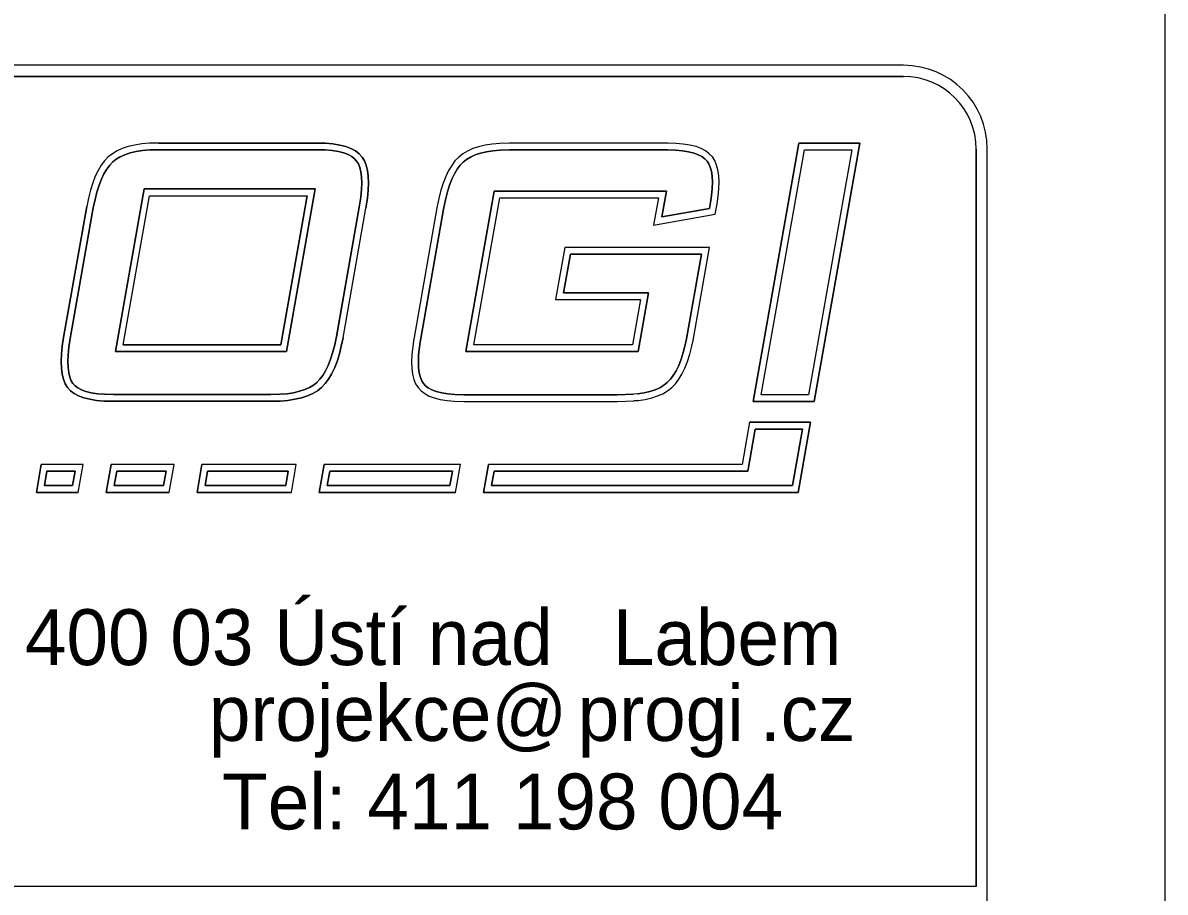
# Model space of a CAD drawing. Extents: x 377 to 692, y 94 to 238.
# Drawn here: x 672.83 to 692.24, y 115.67 to 130.46 of the extents above; entities that cross this region are included whole.
import ezdxf

# ---------------------------------------------------------------- set-up
doc = ezdxf.new("R2010")
doc.units = 0
doc.layers.add('000_rozpiska', color=7, linetype='Continuous')

msp = doc.modelspace()

# ---------------------------------------------------------------- linework, layer by layer
at = {"layer": '000_rozpiska'}
for p, q in [((692.243, 93.878), (692.243, 238.378)), ((687.796, 129.736), (601.346, 129.736)), ((687.796, 129.736), (601.346, 129.736)), ((687.796, 129.546), (660.721, 129.546)), ((680.575, 128.352), (680.475, 128.319)), ((680.687, 128.378), (680.575, 128.352)), ((680.805, 128.396), (680.687, 128.378)), ((680.938, 128.408), (680.805, 128.396)), ((681.097, 128.411), (680.938, 128.408)), ((683.794, 128.411), (681.097, 128.411)), ((683.928, 128.408), (683.794, 128.411)), ((684.052, 128.397), (683.928, 128.408)), ((684.165, 128.379), (684.052, 128.397)), ((684.27, 128.353), (684.165, 128.379)), ((684.356, 128.32), (684.27, 128.353)), ((685.242, 124.021), (686.015, 128.411)), ((686.015, 128.411), (687.052, 128.411)), ((687.052, 128.411), (686.279, 124.021)), ((674.357, 128.093), (674.416, 128.139)), ((674.416, 128.139), (674.482, 128.179)), ((674.482, 128.179), (674.56, 128.215)), ((674.56, 128.215), (674.651, 128.245)), ((674.651, 128.245), (674.752, 128.268)), ((674.752, 128.268), (674.864, 128.286)), ((674.864, 128.286), (674.988, 128.296)), ((674.988, 128.296), (675.142, 128.3)), ((675.142, 128.3), (677.833, 128.3)), ((677.833, 128.3), (677.966, 128.296)), ((677.966, 128.296), (678.086, 128.286)), ((678.086, 128.286), (678.192, 128.269)), ((678.192, 128.269), (678.282, 128.245)), ((678.282, 128.245), (678.356, 128.218)), ((678.356, 128.218), (678.42, 128.184)), ((678.42, 128.184), (678.465, 128.148)), ((678.465, 128.148), (678.502, 128.107)), ((680.236, 128.175), (680.173, 128.109)), ((680.306, 128.23), (680.236, 128.175)), ((680.384, 128.278), (680.306, 128.23)), ((680.438, 128.176), (680.371, 128.136)), ((680.475, 128.319), (680.384, 128.278)), ((680.517, 128.213), (680.438, 128.176)), ((680.606, 128.242), (680.517, 128.213)), ((680.709, 128.266), (680.606, 128.242)), ((680.819, 128.283), (680.709, 128.266)), ((680.944, 128.294), (680.819, 128.283)), ((681.098, 128.297), (680.944, 128.294)), ((683.792, 128.297), (681.098, 128.297)), ((683.921, 128.294), (683.792, 128.297)), ((684.038, 128.284), (683.921, 128.294)), ((684.142, 128.267), (684.038, 128.284)), ((684.236, 128.244), (684.142, 128.267)), ((684.309, 128.216), (684.236, 128.244)), ((684.371, 128.184), (684.309, 128.216)), ((684.432, 128.28), (684.356, 128.32)), ((684.42, 128.148), (684.371, 128.184)), ((684.458, 128.107), (684.42, 128.148)), ((684.496, 128.233), (684.432, 128.28)), ((684.549, 128.177), (684.496, 128.233)), ((684.588, 128.115), (684.549, 128.177)), ((685.378, 124.135), (686.111, 128.297)), ((686.111, 128.297), (686.916, 128.297)), ((686.916, 128.297), (686.183, 124.135)), ((689.031, 115.77), (689.031, 128.311)), ((689.221, 98.325), (689.221, 128.311)), ((689.221, 98.325), (689.221, 128.311)), ((674.207, 127.893), (674.255, 127.972)), ((674.255, 127.972), (674.305, 128.038)), ((674.305, 128.038), (674.357, 128.093)), ((678.502, 128.107), (678.532, 128.059)), ((678.532, 128.059), (678.555, 128)), ((678.555, 128), (678.574, 127.924)), ((680.064, 127.946), (680.015, 127.845)), ((680.117, 128.034), (680.064, 127.946)), ((680.173, 128.109), (680.117, 128.034)), ((680.212, 127.97), (680.165, 127.892)), ((680.261, 128.035), (680.212, 127.97)), ((680.313, 128.09), (680.261, 128.035)), ((680.371, 128.136), (680.313, 128.09)), ((684.487, 128.062), (684.458, 128.107)), ((684.512, 128.003), (684.487, 128.062)), ((684.531, 127.934), (684.512, 128.003)), ((684.62, 128.04), (684.588, 128.115)), ((684.643, 127.958), (684.62, 128.04)), ((684.657, 127.862), (684.643, 127.958)), ((674.123, 127.698), (674.164, 127.802)), ((674.164, 127.802), (674.207, 127.893)), ((678.574, 127.924), (678.585, 127.838)), ((678.585, 127.838), (678.589, 127.735)), ((680.015, 127.845), (679.972, 127.732)), ((680.12, 127.799), (680.08, 127.695)), ((680.165, 127.892), (680.12, 127.799)), ((684.543, 127.85), (684.531, 127.934)), ((684.549, 127.751), (684.543, 127.85)), ((684.546, 127.643), (684.549, 127.751)), ((684.663, 127.752), (684.657, 127.862)), ((684.659, 127.636), (684.663, 127.752)), ((674.055, 127.453), (674.087, 127.581)), ((674.087, 127.581), (674.123, 127.698)), ((674.401, 124.868), (674.888, 127.633)), ((674.888, 127.633), (677.796, 127.633)), ((677.309, 124.868), (677.796, 127.633)), ((678.584, 127.623), (678.572, 127.492)), ((678.589, 127.735), (678.584, 127.623)), ((679.935, 127.613), (679.899, 127.472)), ((679.972, 127.732), (679.935, 127.613)), ((680.044, 127.582), (680.01, 127.447)), ((680.08, 127.695), (680.044, 127.582)), ((680.357, 124.868), (680.838, 127.596)), ((680.838, 127.596), (683.766, 127.596)), ((683.766, 127.596), (683.689, 127.159)), ((684.534, 127.524), (684.546, 127.643)), ((684.647, 127.51), (684.659, 127.636)), ((674.026, 127.313), (674.055, 127.453)), ((674.536, 124.982), (674.983, 127.519)), ((674.983, 127.519), (677.66, 127.519)), ((677.213, 124.982), (677.66, 127.519)), ((678.572, 127.492), (678.546, 127.323)), ((679.882, 127.39), (679.866, 127.312)), ((679.899, 127.472), (679.882, 127.39)), ((679.994, 127.367), (679.978, 127.29)), ((680.01, 127.447), (679.994, 127.367)), ((680.493, 124.982), (680.933, 127.482)), ((680.933, 127.482), (683.63, 127.482)), ((683.63, 127.482), (683.548, 127.018)), ((684.499, 127.303), (684.516, 127.401)), ((684.516, 127.401), (684.534, 127.524)), ((684.597, 127.205), (684.628, 127.383)), ((684.628, 127.383), (684.647, 127.51)), ((673.522, 125.109), (673.914, 127.336)), ((673.635, 125.091), (674.026, 127.313)), ((678.546, 127.323), (678.158, 125.12)), ((678.271, 125.101), (678.659, 127.306)), ((679.866, 127.312), (679.478, 125.11)), ((679.978, 127.29), (679.591, 125.093)), ((683.548, 127.018), (684.597, 127.205)), ((683.689, 127.159), (684.499, 127.303)), ((682.038, 126.637), (681.883, 125.755)), ((684.497, 126.637), (682.038, 126.637)), ((684.219, 125.059), (684.497, 126.637)), ((682.134, 126.523), (682.019, 125.869)), ((684.361, 126.523), (682.134, 126.523)), ((684.107, 125.082), (684.361, 126.523)), ((682.019, 125.869), (683.461, 125.869)), ((683.461, 125.869), (683.285, 124.868)), ((681.883, 125.755), (683.326, 125.755)), ((683.326, 125.755), (683.189, 124.982)), ((673.612, 124.944), (673.635, 125.091)), ((678.159, 125.125), (678.129, 124.983)), ((679.47, 125.05), (679.456, 124.955)), ((679.478, 125.11), (679.47, 125.05)), ((679.583, 125.034), (679.569, 124.941)), ((679.591, 125.093), (679.583, 125.034)), ((684.085, 124.985), (684.107, 125.082)), ((684.196, 124.958), (684.219, 125.059)), ((673.599, 124.813), (673.612, 124.944)), ((674.401, 124.868), (677.309, 124.868)), ((674.536, 124.982), (677.213, 124.982)), ((678.099, 124.861), (678.06, 124.738)), ((678.129, 124.983), (678.099, 124.861)), ((679.456, 124.955), (679.442, 124.82)), ((679.569, 124.941), (679.556, 124.812)), ((683.285, 124.868), (680.357, 124.868)), ((683.189, 124.982), (680.493, 124.982)), ((684.015, 124.736), (684.052, 124.853)), ((684.052, 124.853), (684.085, 124.985)), ((684.162, 124.822), (684.196, 124.958)), ((673.594, 124.698), (673.599, 124.813)), ((673.598, 124.595), (673.594, 124.698)), ((678.06, 124.738), (678.019, 124.633)), ((679.442, 124.82), (679.437, 124.698)), ((679.437, 124.698), (679.441, 124.584)), ((679.556, 124.812), (679.552, 124.698)), ((679.552, 124.698), (679.555, 124.593)), ((683.975, 124.63), (684.015, 124.736)), ((684.079, 124.585), (684.123, 124.699)), ((684.123, 124.699), (684.162, 124.822)), ((673.609, 124.507), (673.598, 124.595)), ((673.628, 124.433), (673.609, 124.507)), ((677.928, 124.463), (677.879, 124.397)), ((677.975, 124.541), (677.928, 124.463)), ((678.019, 124.633), (677.975, 124.541)), ((679.441, 124.584), (679.454, 124.483)), ((679.454, 124.483), (679.476, 124.394)), ((679.555, 124.593), (679.566, 124.504)), ((679.566, 124.504), (679.585, 124.429)), ((683.835, 124.396), (683.884, 124.461)), ((683.884, 124.461), (683.93, 124.538)), ((683.93, 124.538), (683.975, 124.63)), ((683.978, 124.398), (684.031, 124.484)), ((684.031, 124.484), (684.079, 124.585)), ((673.652, 124.373), (673.628, 124.433)), ((673.68, 124.326), (673.652, 124.373)), ((673.716, 124.287), (673.68, 124.326)), ((673.764, 124.251), (673.716, 124.287)), ((677.702, 124.258), (677.622, 124.222)), ((677.769, 124.297), (677.702, 124.258)), ((677.826, 124.342), (677.769, 124.297)), ((677.879, 124.397), (677.826, 124.342)), ((679.476, 124.394), (679.505, 124.321)), ((679.505, 124.321), (679.545, 124.255)), ((679.545, 124.255), (679.596, 124.199)), ((679.585, 124.429), (679.607, 124.372)), ((679.607, 124.372), (679.637, 124.324)), ((679.637, 124.324), (679.673, 124.284)), ((679.673, 124.284), (679.72, 124.25)), ((683.653, 124.253), (683.724, 124.294)), ((683.724, 124.294), (683.781, 124.34)), ((683.781, 124.34), (683.835, 124.396)), ((683.788, 124.2), (683.858, 124.255)), ((683.858, 124.255), (683.922, 124.322)), ((683.922, 124.322), (683.978, 124.398)), ((673.824, 124.219), (673.764, 124.251)), ((673.9, 124.191), (673.824, 124.219)), ((673.99, 124.168), (673.9, 124.191)), ((674.096, 124.151), (673.99, 124.168)), ((674.214, 124.141), (674.096, 124.151)), ((674.37, 124.137), (674.214, 124.141)), ((677.043, 124.137), (674.37, 124.137)), ((677.196, 124.141), (677.043, 124.137)), ((677.319, 124.151), (677.196, 124.141)), ((677.431, 124.169), (677.319, 124.151)), ((677.533, 124.192), (677.431, 124.169)), ((677.622, 124.222), (677.533, 124.192)), ((679.596, 124.199), (679.659, 124.153)), ((679.659, 124.153), (679.735, 124.112)), ((679.72, 124.25), (679.782, 124.216)), ((679.735, 124.112), (679.822, 124.079)), ((679.782, 124.216), (679.856, 124.188)), ((679.822, 124.079), (679.924, 124.054)), ((679.856, 124.188), (679.947, 124.166)), ((679.947, 124.166), (680.053, 124.149)), ((680.053, 124.149), (680.172, 124.139)), ((680.172, 124.139), (680.325, 124.135)), ((680.325, 124.135), (682.932, 124.135)), ((682.932, 124.135), (683.207, 124.144)), ((683.274, 124.149), (683.207, 124.144)), ((683.274, 124.149), (683.387, 124.166)), ((683.387, 124.166), (683.486, 124.189)), ((683.408, 124.054), (683.517, 124.079)), ((683.486, 124.189), (683.576, 124.219)), ((683.517, 124.079), (683.617, 124.113)), ((683.576, 124.219), (683.653, 124.253)), ((683.617, 124.113), (683.705, 124.151)), ((683.705, 124.151), (683.788, 124.2)), ((686.183, 124.135), (685.378, 124.135)), ((679.924, 124.054), (680.039, 124.036)), ((680.039, 124.036), (680.166, 124.025)), ((680.166, 124.025), (680.324, 124.021)), ((680.324, 124.021), (682.934, 124.021)), ((682.934, 124.021), (683.213, 124.03)), ((683.287, 124.036), (683.213, 124.03)), ((683.287, 124.036), (683.408, 124.054)), ((686.279, 124.021), (685.242, 124.021)), ((685.179, 123.665), (685.053, 122.949)), ((685.275, 123.551), (685.149, 122.835)), ((685.179, 123.665), (686.216, 123.665)), ((685.275, 123.551), (686.08, 123.551)), ((686.08, 123.551), (685.911, 122.588)), ((686.216, 123.665), (686.006, 122.474)), ((673.058, 122.474), (673.142, 122.949)), ((673.854, 122.949), (673.142, 122.949)), ((673.77, 122.474), (673.854, 122.949)), ((674.245, 122.474), (674.329, 122.949)), ((675.398, 122.949), (674.329, 122.949)), ((675.314, 122.474), (675.398, 122.949)), ((675.789, 122.474), (675.873, 122.949)), ((677.476, 122.949), (675.873, 122.949)), ((677.392, 122.474), (677.476, 122.949)), ((677.867, 122.474), (677.951, 122.949)), ((680.267, 122.949), (677.951, 122.949)), ((680.183, 122.474), (680.267, 122.949)), ((680.658, 122.474), (680.742, 122.949)), ((685.053, 122.949), (680.742, 122.949)), ((673.194, 122.588), (673.237, 122.835)), ((673.718, 122.835), (673.237, 122.835)), ((673.675, 122.588), (673.718, 122.835)), ((674.381, 122.588), (674.425, 122.835)), ((675.262, 122.835), (674.425, 122.835)), ((675.218, 122.588), (675.262, 122.835)), ((675.925, 122.588), (675.968, 122.835)), ((677.34, 122.835), (675.968, 122.835)), ((677.297, 122.588), (677.34, 122.835)), ((678.003, 122.588), (678.047, 122.835)), ((680.131, 122.835), (678.047, 122.835)), ((680.087, 122.588), (680.131, 122.835)), ((680.794, 122.588), (680.837, 122.835)), ((685.149, 122.835), (680.837, 122.835)), ((673.675, 122.588), (673.194, 122.588)), ((675.218, 122.588), (674.381, 122.588)), ((677.297, 122.588), (675.925, 122.588)), ((680.087, 122.588), (678.003, 122.588)), ((685.911, 122.588), (680.794, 122.588)), ((673.77, 122.474), (673.058, 122.474)), ((675.314, 122.474), (674.245, 122.474)), ((677.392, 122.474), (675.789, 122.474)), ((680.183, 122.474), (677.867, 122.474)), ((686.006, 122.474), (680.658, 122.474)), ((689.031, 115.77), (660.721, 115.77))]:
    msp.add_line(p, q, dxfattribs=at)
for points in [[(660.721, 115.77), (660.721, 129.546), (687.796, 129.546)], [(678.216, 128.38), (678.1, 128.399), (677.972, 128.41), (677.836, 128.414), (675.141, 128.414), (674.982, 128.41), (674.851, 128.399), (674.73, 128.38), (674.62, 128.355), (674.519, 128.321), (674.429, 128.28), (674.351, 128.233), (674.279, 128.177), (674.217, 128.111), (674.16, 128.036), (674.107, 127.947), (674.06, 127.848), (674.016, 127.736), (673.977, 127.612), (673.944, 127.478), (673.914, 127.336), (673.522, 125.109), (673.499, 124.959), (673.485, 124.821), (673.48, 124.698), (673.484, 124.586), (673.497, 124.486), (673.519, 124.398), (673.549, 124.321), (673.589, 124.257), (673.639, 124.202), (673.702, 124.155), (673.777, 124.115), (673.866, 124.082), (673.967, 124.056), (674.082, 124.038), (674.208, 124.027), (674.367, 124.023), (677.044, 124.023), (677.202, 124.027), (677.332, 124.038), (677.453, 124.057), (677.564, 124.083), (677.664, 124.115), (677.755, 124.156), (677.834, 124.203), (677.903, 124.257), (677.966, 124.323), (678.023, 124.399), (678.075, 124.486), (678.124, 124.587), (678.168, 124.7), (678.209, 124.83), (678.24, 124.958), (678.271, 125.101), (678.659, 127.306), (678.685, 127.478), (678.698, 127.615), (678.703, 127.735), (678.699, 127.848), (678.686, 127.945), (678.664, 128.035), (678.634, 128.11), (678.594, 128.175), (678.543, 128.232), (678.482, 128.28), (678.403, 128.322), (678.317, 128.354), (678.216, 128.38)], [(675.141, 128.414), (674.982, 128.41), (674.851, 128.399), (674.73, 128.38), (674.62, 128.355), (674.519, 128.321), (674.429, 128.28), (674.351, 128.233), (674.279, 128.177), (674.217, 128.111), (674.16, 128.036), (674.107, 127.947), (674.06, 127.848), (674.016, 127.736), (673.977, 127.612), (673.944, 127.478), (673.914, 127.336)], [(675.141, 128.414), (677.836, 128.414), (677.972, 128.41), (678.1, 128.399), (678.216, 128.38), (678.317, 128.354), (678.403, 128.322), (678.482, 128.28), (678.543, 128.232), (678.594, 128.175), (678.634, 128.11), (678.664, 128.035), (678.686, 127.945), (678.699, 127.848), (678.703, 127.735), (678.698, 127.615), (678.685, 127.478), (678.659, 127.306)], [(684.27, 128.353), (684.165, 128.379), (684.052, 128.397), (683.928, 128.408), (683.794, 128.411), (681.097, 128.411), (680.938, 128.408), (680.805, 128.396), (680.687, 128.378), (680.575, 128.352), (680.475, 128.319), (680.384, 128.278), (680.306, 128.23), (680.236, 128.175), (680.173, 128.109), (680.117, 128.034), (680.064, 127.946), (680.015, 127.845), (679.972, 127.732), (679.935, 127.613), (679.899, 127.472), (679.882, 127.39), (679.866, 127.312), (679.478, 125.11), (679.47, 125.05), (679.456, 124.955), (679.442, 124.82), (679.437, 124.698), (679.441, 124.584), (679.454, 124.483), (679.476, 124.394), (679.505, 124.321), (679.545, 124.255), (679.596, 124.199), (679.659, 124.153), (679.735, 124.112), (679.822, 124.079), (679.924, 124.054), (680.039, 124.036), (680.166, 124.025), (680.324, 124.021), (682.934, 124.021), (683.213, 124.03), (683.287, 124.036), (683.408, 124.054), (683.517, 124.079), (683.617, 124.113), (683.705, 124.151), (683.788, 124.2), (683.858, 124.255), (683.922, 124.322), (683.978, 124.398), (684.031, 124.484), (684.079, 124.585), (684.123, 124.699), (684.162, 124.822), (684.196, 124.958), (684.219, 125.059), (684.497, 126.637), (682.038, 126.637), (681.883, 125.755), (683.326, 125.755), (683.189, 124.982), (680.493, 124.982), (680.933, 127.482), (683.63, 127.482), (683.548, 127.018), (684.597, 127.205), (684.628, 127.383), (684.647, 127.51), (684.659, 127.636), (684.663, 127.752), (684.657, 127.862), (684.643, 127.958), (684.62, 128.04), (684.588, 128.115), (684.549, 128.177), (684.496, 128.233), (684.432, 128.28), (684.356, 128.32), (684.27, 128.353)], [(687.052, 128.411), (686.015, 128.411), (685.242, 124.021), (686.279, 124.021), (687.052, 128.411)], [(689.031, 128.311), (689.031, 115.77), (660.721, 115.77)], [(678.589, 127.735), (678.585, 127.838), (678.574, 127.924), (678.555, 128), (678.532, 128.059), (678.502, 128.107), (678.465, 128.148), (678.42, 128.184), (678.356, 128.218), (678.282, 128.245), (678.192, 128.269), (678.086, 128.286), (677.966, 128.296), (677.833, 128.3), (675.142, 128.3), (674.988, 128.296), (674.864, 128.286), (674.752, 128.268), (674.651, 128.245), (674.56, 128.215), (674.482, 128.179), (674.416, 128.139), (674.357, 128.093), (674.305, 128.038), (674.255, 127.972), (674.207, 127.893), (674.164, 127.802), (674.123, 127.698), (674.087, 127.581), (674.055, 127.453), (674.026, 127.313), (673.635, 125.091), (673.612, 124.944), (673.599, 124.813), (673.594, 124.698), (673.598, 124.595), (673.609, 124.507), (673.628, 124.433), (673.652, 124.373), (673.68, 124.326), (673.716, 124.287), (673.764, 124.251), (673.824, 124.219), (673.9, 124.191), (673.99, 124.168), (674.096, 124.151), (674.214, 124.141), (674.37, 124.137), (677.043, 124.137), (677.196, 124.141), (677.319, 124.151), (677.431, 124.169), (677.533, 124.192), (677.622, 124.222), (677.702, 124.258), (677.769, 124.297), (677.826, 124.342), (677.879, 124.397), (677.928, 124.463), (677.975, 124.541), (678.019, 124.633), (678.06, 124.738), (678.099, 124.861), (678.129, 124.983), (678.159, 125.122), (678.546, 127.323), (678.572, 127.492), (678.584, 127.623), (678.589, 127.735)], [(677.833, 128.3), (677.966, 128.296), (678.086, 128.286), (678.192, 128.269), (678.282, 128.245), (678.356, 128.218), (678.42, 128.184), (678.465, 128.148), (678.502, 128.107), (678.532, 128.059), (678.555, 128), (678.574, 127.924), (678.585, 127.838), (678.589, 127.735), (678.584, 127.623), (678.572, 127.492), (678.546, 127.323), (678.159, 125.122), (678.129, 124.983), (678.099, 124.861), (678.06, 124.738), (678.019, 124.633), (677.975, 124.541), (677.928, 124.463), (677.879, 124.397), (677.826, 124.342), (677.769, 124.297), (677.702, 124.258), (677.622, 124.222), (677.533, 124.192), (677.431, 124.169), (677.319, 124.151), (677.196, 124.141), (677.043, 124.137), (674.37, 124.137), (674.214, 124.141), (674.096, 124.151), (673.99, 124.168), (673.9, 124.191), (673.824, 124.219), (673.764, 124.251), (673.716, 124.287), (673.68, 124.326), (673.652, 124.373), (673.628, 124.433), (673.609, 124.507), (673.598, 124.595), (673.594, 124.698), (673.599, 124.813), (673.612, 124.944), (673.635, 125.091), (674.026, 127.313), (674.055, 127.453), (674.087, 127.581), (674.123, 127.698), (674.164, 127.802), (674.207, 127.893), (674.255, 127.972), (674.305, 128.038), (674.357, 128.093), (674.416, 128.139), (674.482, 128.179), (674.56, 128.215), (674.651, 128.245), (674.752, 128.268), (674.864, 128.286), (674.988, 128.296), (675.142, 128.3), (677.833, 128.3)], [(683.792, 128.297), (683.921, 128.294), (684.038, 128.284), (684.142, 128.267), (684.236, 128.244), (684.309, 128.216), (684.371, 128.184), (684.42, 128.148), (684.458, 128.107), (684.487, 128.062), (684.512, 128.003), (684.531, 127.934), (684.543, 127.85), (684.549, 127.751), (684.546, 127.643), (684.534, 127.524), (684.516, 127.401), (684.499, 127.303), (683.689, 127.159), (683.766, 127.596), (680.838, 127.596), (680.357, 124.868), (683.285, 124.868), (683.461, 125.869), (682.019, 125.869), (682.134, 126.523), (684.361, 126.523), (684.107, 125.082), (684.085, 124.985), (684.052, 124.853), (684.015, 124.736), (683.975, 124.63), (683.93, 124.538), (683.884, 124.461), (683.835, 124.396), (683.781, 124.34), (683.724, 124.294), (683.653, 124.253), (683.576, 124.219), (683.486, 124.189), (683.387, 124.166), (683.274, 124.149), (683.207, 124.144), (682.932, 124.135), (680.325, 124.135), (680.172, 124.139), (680.053, 124.149), (679.947, 124.166), (679.856, 124.188), (679.782, 124.216), (679.72, 124.25), (679.673, 124.284), (679.637, 124.324), (679.607, 124.372), (679.585, 124.429), (679.566, 124.504), (679.555, 124.593), (679.552, 124.698), (679.556, 124.812), (679.569, 124.941), (679.583, 125.034), (679.591, 125.093), (679.978, 127.29), (679.994, 127.367), (680.01, 127.447), (680.044, 127.582), (680.08, 127.695), (680.12, 127.799), (680.165, 127.892), (680.212, 127.97), (680.261, 128.035), (680.313, 128.09), (680.371, 128.136), (680.438, 128.176), (680.517, 128.213), (680.606, 128.242), (680.709, 128.266), (680.819, 128.283), (680.944, 128.294), (681.098, 128.297), (683.792, 128.297)], [(686.916, 128.297), (686.183, 124.135), (685.378, 124.135), (686.111, 128.297), (686.916, 128.297)], [(677.796, 127.633), (677.309, 124.868), (674.401, 124.868), (674.888, 127.633), (677.796, 127.633)], [(677.796, 127.633), (674.888, 127.633), (674.401, 124.868), (677.309, 124.868), (677.796, 127.633)], [(677.66, 127.519), (677.213, 124.982), (674.536, 124.982), (674.983, 127.519), (677.66, 127.519)], [(674.367, 124.023), (674.208, 124.027), (674.082, 124.038), (673.967, 124.056), (673.866, 124.082), (673.777, 124.115), (673.702, 124.155), (673.639, 124.202), (673.589, 124.257), (673.549, 124.321), (673.519, 124.398), (673.497, 124.486), (673.484, 124.586), (673.48, 124.698), (673.485, 124.821), (673.499, 124.959), (673.522, 125.109)], [(678.271, 125.101), (678.24, 124.958), (678.209, 124.83), (678.168, 124.7), (678.124, 124.587), (678.075, 124.486), (678.023, 124.399), (677.966, 124.323), (677.903, 124.257), (677.834, 124.203), (677.755, 124.156), (677.664, 124.115), (677.564, 124.083), (677.453, 124.057), (677.332, 124.038), (677.202, 124.027), (677.044, 124.023), (674.367, 124.023)], [(686.216, 123.665), (685.179, 123.665), (685.053, 122.949), (680.742, 122.949), (680.658, 122.474), (686.006, 122.474), (686.216, 123.665)], [(686.08, 123.551), (685.911, 122.588), (680.794, 122.588), (680.837, 122.835), (685.149, 122.835), (685.275, 123.551), (686.08, 123.551)], [(686.08, 123.551), (685.275, 123.551), (685.149, 122.835), (680.837, 122.835), (680.794, 122.588), (685.911, 122.588), (686.08, 123.551)], [(673.854, 122.949), (673.142, 122.949), (673.058, 122.474), (673.77, 122.474), (673.854, 122.949)], [(675.398, 122.949), (674.329, 122.949), (674.245, 122.474), (675.314, 122.474), (675.398, 122.949)], [(677.476, 122.949), (675.873, 122.949), (675.789, 122.474), (677.392, 122.474), (677.476, 122.949)], [(680.267, 122.949), (677.951, 122.949), (677.867, 122.474), (680.183, 122.474), (680.267, 122.949)], [(673.718, 122.835), (673.675, 122.588), (673.194, 122.588), (673.237, 122.835), (673.718, 122.835)], [(673.718, 122.835), (673.237, 122.835), (673.194, 122.588), (673.675, 122.588), (673.718, 122.835)], [(675.262, 122.835), (675.218, 122.588), (674.381, 122.588), (674.425, 122.835), (675.262, 122.835)], [(675.262, 122.835), (674.425, 122.835), (674.381, 122.588), (675.218, 122.588), (675.262, 122.835)], [(677.34, 122.835), (677.297, 122.588), (675.925, 122.588), (675.968, 122.835), (677.34, 122.835)], [(677.34, 122.835), (675.968, 122.835), (675.925, 122.588), (677.297, 122.588), (677.34, 122.835)], [(680.131, 122.835), (680.087, 122.588), (678.003, 122.588), (678.047, 122.835), (680.131, 122.835)], [(680.131, 122.835), (678.047, 122.835), (678.003, 122.588), (680.087, 122.588), (680.131, 122.835)]]:
    msp.add_lwpolyline(points, dxfattribs=at)
for radius, start in [(1.425, 0), (1.425, 360), (1.235, 0), (1.235, 360)]:
    msp.add_arc((687.796, 128.311), radius, start, 90, dxfattribs=at)

# ---------------------------------------------------------------- texts
for s, p in [('400 03 Ústí nad', (672.863, 119.536)), ('Labem', (682.856, 119.536)), ('projekce@', (675.99, 118.247)), ('progi', (682.258, 118.247)), ('.cz', (685.356, 118.247)), ('Tel: 411 198 004', (676.214, 116.742))]:
    msp.add_text(s, height=0.95, dxfattribs=at).set_placement(p)

doc.saveas('drawing.dxf')
